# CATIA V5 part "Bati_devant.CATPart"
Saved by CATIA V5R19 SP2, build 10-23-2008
Part number: Bati devant
Bounding box of the stored display mesh (mm): x -40 to 20, y -50 to 50, z 0 to 338
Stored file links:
  C:\Users\Romain\Documents\IFMA\2A\cours\S3\Projet CFAO-IAO\IAO\Catia\Bati\Bati_devant.CATPart
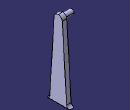
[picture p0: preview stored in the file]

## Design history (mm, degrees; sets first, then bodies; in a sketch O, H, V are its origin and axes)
Body1 (main body)
  Sketch1 on yz-plane, origin (0, 0, 0), H (0, 1, 0), V (0, 0, 1)
    line L1 (0, 0) -> (50, 0)
    point P1 (50, 0)
    arc A1 centre (50, 12.8589) radius 12.8589 from (37.1658, 12.0616) to (50, 0) ccw
    point P3 (37.1658, 12.0616)
    line L2 (37.1658, 12.0616) -> (17.9654, 321.1161)
    point P4 (17.9654, 321.1161)
    arc A2 centre (0, 320) radius 18 from (17.9654, 321.1161) to (0, 338) ccw
    point P5 (0, 320)
    point P6 (0, 338)
    reference intersected line E1 through (0, 0) direction (-1, 0) from xy-plane
    point P7 (-50, 0)
    point P9 (-37.1658, 12.0616)
    point P10 (-17.9654, 321.1161)
    point P12 (0, 338)
    point P13 (0, 0)
    line L3 (0, 0) -> (-50, 0)
    arc A3 centre (-50, 12.8589) radius 12.8589 from (-37.1658, 12.0616) to (-50, 0) cw
    line L4 (-37.1658, 12.0616) -> (-17.9654, 321.1161)
    arc A4 centre (0, 320) radius 18 from (-17.9654, 321.1161) to (0, 338) cw
    length L1 = 50
    distance P5 V = 0
    distance P5 E1 = 320
    radius A2 = 18
    horizontal: L1 H
    tangency: A1 L1, A2 L2, L2 A1
    coincidence: P6 V, O P13, P6 P12
    symmetry: P1 P7 V, P3 P9 V, P4 P10 V, P6 P12 V, O P13 V, L1 L3 V, A1 A3 V, L2 L4 V, A2 A4 V
  Pad1: profile Sketch1, direction (1, 0, 0), length 20
  Sketch2 on end face of Pad1, origin (20, 0, 0), H (0, 1, 0), V (0, 0, 1)
    circle A1 centre (0, 319.873) radius 10
    point P1 (0, 319.873)
    reference intersected line E1 (-115, 0) -> (115, 0) from face of DatumSurface1
    radius A1 = 10
    distance A1 E1 = 309.873
    coincidence: P1 V
  Pad2: profile Sketch2, direction (-1, 0, 0), length 60
  DatumSurface1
